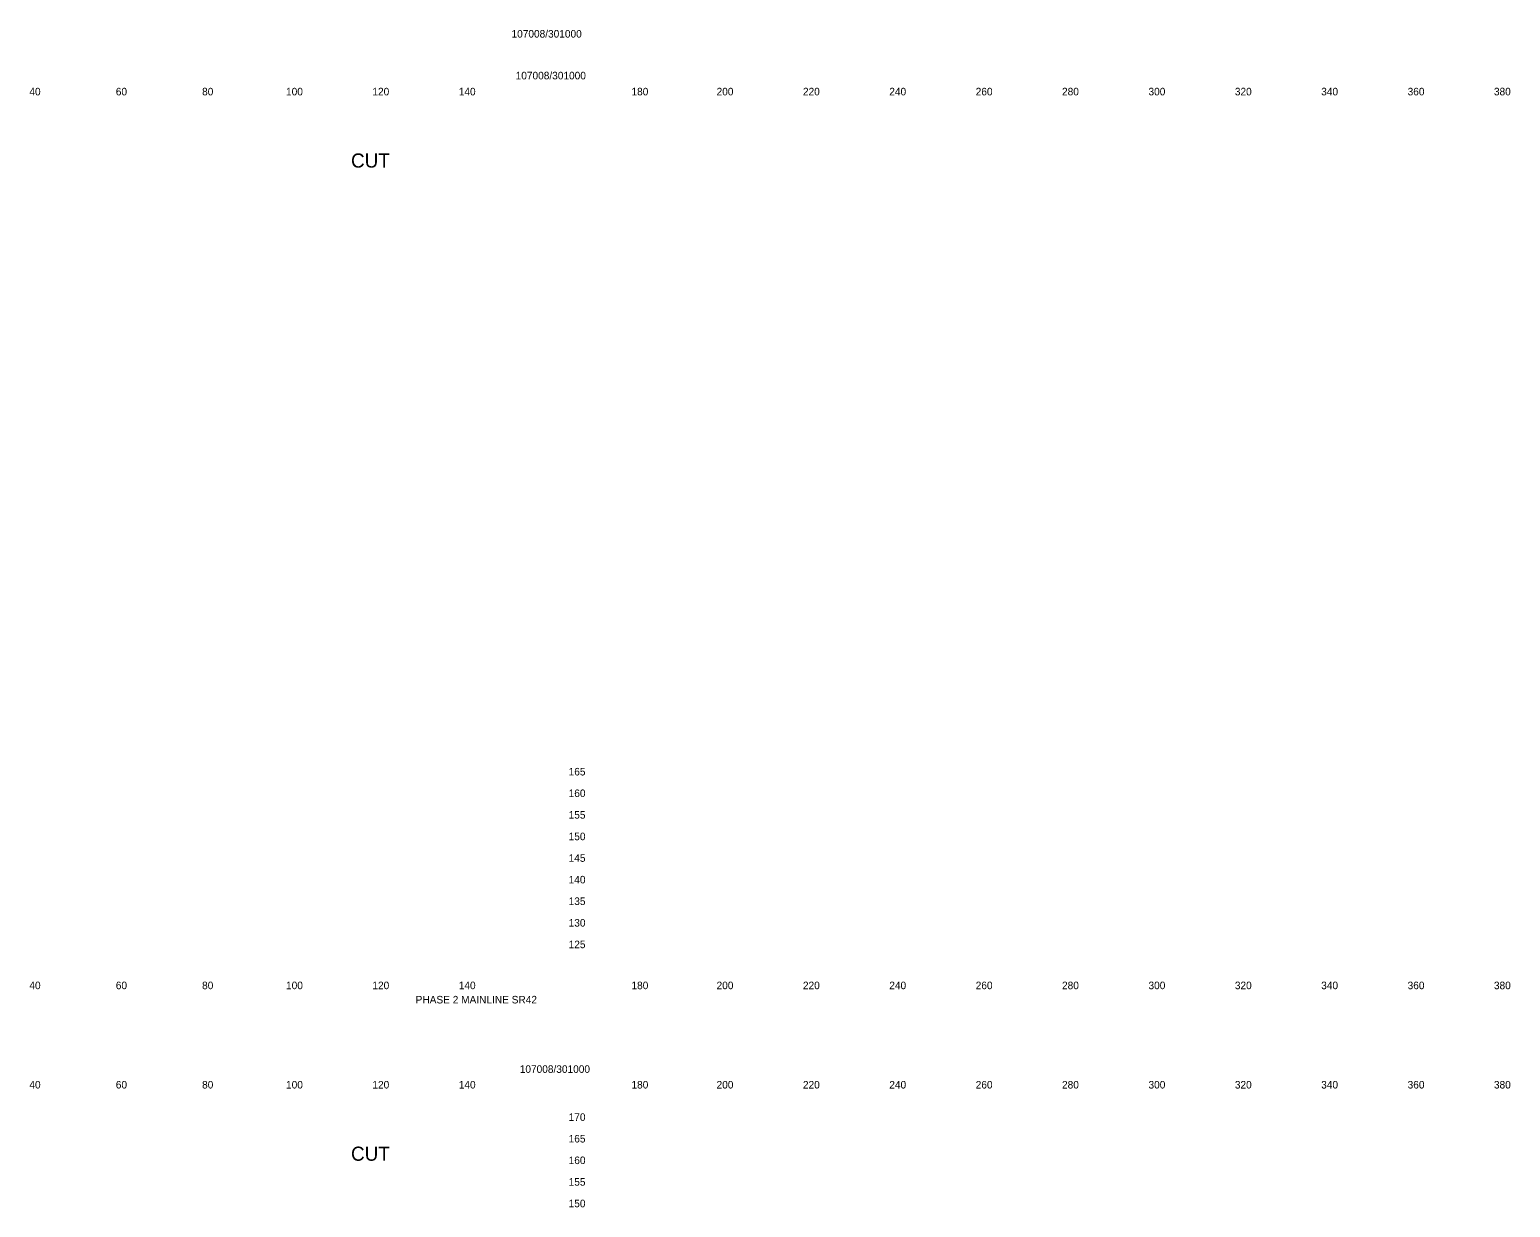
# Model space of a CAD drawing. Extents: x 21281 to 22024, y 6472 to 15208.
# Drawn here: x 21681.3 to 22024.2, y 14934.8 to 15207.6 of the extents above; entities that cross this region are included whole.
import ezdxf

# ---------------------------------------------------------------- set-up
doc = ezdxf.new("R2010")
doc.units = 0
doc.layers.add('XS_SHEET_LABELS_ELEVATION', color=7, linetype='Continuous')
doc.layers.add('XS_SHEET_LABELS_OFFSET', color=7, linetype='Continuous')

msp = doc.modelspace()

# ---------------------------------------------------------------- texts
at = {"layer": 'XS_SHEET_LABELS_ELEVATION'}
for s, p in [('  165  ', (21804.84, 15034.84)), ('  160  ', (21804.84, 15029.84)), ('  155  ', (21804.84, 15024.84)), ('  150  ', (21804.84, 15019.84)), ('  145  ', (21804.84, 15014.84)), ('  140  ', (21804.84, 15009.84)), ('  135  ', (21804.84, 15004.84)), ('  130  ', (21804.84, 14999.84)), ('  125  ', (21804.84, 14994.84)), ('  170  ', (21804.84, 14954.84)), ('  165  ', (21804.84, 14949.84)), ('  160  ', (21804.84, 14944.84)), ('  155  ', (21804.84, 14939.84)), ('  150  ', (21804.84, 14934.84))]:
    msp.add_text(s, height=1.75, dxfattribs=at).set_placement(p)
at = {"layer": 'XS_SHEET_LABELS_OFFSET'}
for s, height, p in [('107008/301000', 1.75, (21792.91, 15205.72)), ('107008/301000', 1.75, (21793.87, 15196.05)), ('  40  ', 1.75, (21679.95, 15192.34)), ('  60  ', 1.75, (21699.97, 15192.34)), ('  80  ', 1.75, (21719.95, 15192.34)), ('  100  ', 1.75, (21739.39, 15192.34)), ('  120  ', 1.75, (21759.39, 15192.34)), ('  140  ', 1.75, (21779.39, 15192.34)), ('  180  ', 1.75, (21819.39, 15192.34)), ('  200  ', 1.75, (21839.1, 15192.34)), ('  220  ', 1.75, (21859.1, 15192.34)), ('  240  ', 1.75, (21879.1, 15192.34)), ('  260  ', 1.75, (21899.11, 15192.34)), ('  280  ', 1.75, (21919.1, 15192.34)), ('  300  ', 1.75, (21939.13, 15192.34)), ('  320  ', 1.75, (21959.13, 15192.34)), ('  340  ', 1.75, (21979.13, 15192.34)), ('  360  ', 1.75, (21999.14, 15192.34)), ('  380  ', 1.75, (22019.13, 15192.34)), ('CUT', 3.273, (21755.74, 15175.61)), ('  40  ', 1.75, (21679.95, 14985.34)), ('  60  ', 1.75, (21699.97, 14985.34)), ('  80  ', 1.75, (21719.95, 14985.34)), ('  100  ', 1.75, (21739.39, 14985.34)), ('  120  ', 1.75, (21759.39, 14985.34)), ('  140  ', 1.75, (21779.39, 14985.34)), ('  180  ', 1.75, (21819.39, 14985.34)), ('  200  ', 1.75, (21839.1, 14985.34)), ('  220  ', 1.75, (21859.1, 14985.34)), ('  240  ', 1.75, (21879.1, 14985.34)), ('  260  ', 1.75, (21899.11, 14985.34)), ('  280  ', 1.75, (21919.1, 14985.34)), ('  300  ', 1.75, (21939.13, 14985.34)), ('  320  ', 1.75, (21959.13, 14985.34)), ('  340  ', 1.75, (21979.13, 14985.34)), ('  360  ', 1.75, (21999.14, 14985.34)), ('  380  ', 1.75, (22019.13, 14985.34)), ('PHASE 2 MAINLINE SR42', 1.75, (21770.71, 14982.04)), ('107008/301000', 1.75, (21794.82, 14965.96)), ('  40  ', 1.75, (21679.95, 14962.34)), ('  60  ', 1.75, (21699.97, 14962.34)), ('  80  ', 1.75, (21719.95, 14962.34)), ('  100  ', 1.75, (21739.39, 14962.34)), ('  120  ', 1.75, (21759.39, 14962.34)), ('  140  ', 1.75, (21779.39, 14962.34)), ('  180  ', 1.75, (21819.39, 14962.34)), ('  200  ', 1.75, (21839.1, 14962.34)), ('  220  ', 1.75, (21859.1, 14962.34)), ('  240  ', 1.75, (21879.1, 14962.34)), ('  260  ', 1.75, (21899.11, 14962.34)), ('  280  ', 1.75, (21919.1, 14962.34)), ('  300  ', 1.75, (21939.13, 14962.34)), ('  320  ', 1.75, (21959.13, 14962.34)), ('  340  ', 1.75, (21979.13, 14962.34)), ('  360  ', 1.75, (21999.14, 14962.34)), ('  380  ', 1.75, (22019.13, 14962.34)), ('CUT', 3.273, (21755.74, 14945.61))]:
    msp.add_text(s, height=height, dxfattribs=at).set_placement(p)

doc.saveas('drawing.dxf')
